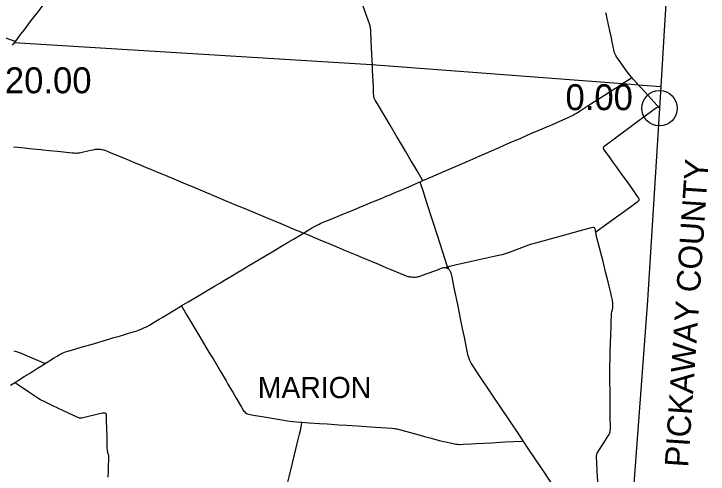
# Model space of a CAD drawing. Extents: x 1597222 to 1925846, y 496284 to 911751.
# Drawn here: x 1727439 to 1756910, y 574335 to 593847 of the extents above; entities that cross this region are included whole.
import ezdxf

# ---------------------------------------------------------------- set-up
doc = ezdxf.new("R2010")
doc.units = 0
for name, color, linetype in [('Default', 7, 'Continuous'), ('GM_X_Adjacent_County_Text', 7, 'Continuous'), ('GM_X_County', 7, 'Continuous'), ('GM_X_County_Road', 7, 'Continuous'), ('GM_X_State_Route', 7, 'Continuous'), ('GM_X_Township', 7, 'Continuous'), ('GM_X_Township_Road', 7, 'Continuous'), ('GM_X_Township_Text', 7, 'Continuous'), ('GM_X_US_Route', 7, 'Continuous')]:
    doc.layers.add(name, color=color, linetype=linetype)

msp = doc.modelspace()

# ---------------------------------------------------------------- linework, layer by layer
at = {"layer": 'Default'}
msp.add_circle((1754847, 589845), 750, dxfattribs=at)
msp.add_circle((1754847, 589845), 750, dxfattribs=at)
msp.add_circle((1754847, 589845), 750, dxfattribs=at)
msp.add_circle((1754847, 589845), 750, dxfattribs=at)
at = {"layer": 'GM_X_County'}
msp.add_lwpolyline([(1724957, 620538), (1728386, 620349), (1731998, 620173), (1732995, 620100), (1742304, 619412), (1747296, 619048), (1751520, 618741), (1756758, 618359), (1755763, 604727), (1755032, 592905), (1754900, 590773), (1754843, 589851), (1754339, 581698), (1753562, 571274), (1753386, 568784), (1753383, 568749), (1753220, 566444), (1752151, 553079)], dxfattribs=at)
at = {"layer": 'GM_X_County_Road'}
for points in [[(1724345, 593802), (1724527, 593740), (1724852, 593628), (1725347, 593455), (1725641, 593354), (1725980, 593232), (1726628, 592999), (1726937, 592890), (1727275, 592768), (1727446, 592708), (1727515, 592688)], [(1751477, 589738), (1751562, 589793), (1751782, 589936), (1752086, 590131), (1752362, 590308), (1752858, 590627), (1753245, 590875), (1753281, 590899)], [(1753281, 590899), (1753507, 591044), (1753611, 591113), (1753665, 591150)], [(1744801, 586780), (1745035, 586882), (1745788, 587207), (1746285, 587422), (1746676, 587591), (1746812, 587650), (1747187, 587814), (1748015, 588172), (1748256, 588276), (1748512, 588388), (1748963, 588584), (1749234, 588701), (1749460, 588798), (1749761, 588929), (1750062, 589058), (1750272, 589150), (1750739, 589351), (1750964, 589452), (1751083, 589507), (1751156, 589545), (1751242, 589593), (1751327, 589644), (1751477, 589738)], [(1727418, 588214), (1727598, 588196), (1727891, 588165), (1728120, 588142), (1728397, 588114), (1728593, 588096), (1728675, 588088), (1728934, 588060), (1729292, 588022), (1729910, 587959), (1730008, 587950), (1730074, 587947), (1730123, 587948), (1730171, 587951), (1730220, 587957), (1730284, 587968), (1730396, 587992), (1730524, 588023), (1730635, 588050), (1730795, 588088), (1730859, 588102), (1730908, 588110), (1730957, 588114), (1731007, 588115), (1731056, 588113), (1731106, 588109), (1731155, 588102), (1731203, 588092), (1731251, 588080), (1731298, 588065), (1731375, 588037), (1731557, 587962), (1731951, 587798), (1732360, 587628), (1732542, 587552), (1732769, 587458), (1733057, 587338), (1733283, 587243), (1733541, 587137), (1733723, 587062), (1733859, 587005), (1734328, 586809), (1734631, 586683), (1735009, 586524), (1735448, 586341), (1735811, 586190), (1736205, 586025), (1736780, 585786), (1737249, 585590), (1737582, 585451), (1738142, 585218), (1738778, 584954), (1739066, 584834), (1739429, 584682), (1739550, 584631), (1739700, 584565), (1739729, 584555)], [(1744684, 586731), (1744795, 586778), (1744801, 586780)], [(1739729, 584555), (1739812, 584604), (1740079, 584764), (1740206, 584839), (1740307, 584894), (1740395, 584938), (1740469, 584973), (1740575, 585017), (1740939, 585165), (1741409, 585359), (1741864, 585546), (1742229, 585695), (1742411, 585770), (1742593, 585845), (1743002, 586013), (1743123, 586064), (1743244, 586114), (1743412, 586182), (1743502, 586220), (1743653, 586284), (1743834, 586361), (1744105, 586479), (1744330, 586577), (1744571, 586683), (1744684, 586731)], [(1745853, 583130), (1745838, 583168), (1745654, 583746), (1745426, 584447), (1745214, 585102), (1745143, 585320), (1744901, 586069), (1744826, 586303), (1744692, 586707), (1744684, 586731)], [(1734547, 581463), (1734840, 581638), (1735178, 581840), (1735572, 582076), (1735952, 582303), (1736178, 582437), (1736375, 582554), (1736643, 582713), (1736910, 582874), (1737079, 582974), (1737445, 583193), (1738093, 583580), (1738404, 583763), (1738615, 583890), (1738840, 584025), (1739079, 584168), (1739305, 584302), (1739729, 584555)], [(1739729, 584555), (1739792, 584532), (1739899, 584489), (1740459, 584255), (1740776, 584121), (1741155, 583965), (1741503, 583820), (1742002, 583611), (1742230, 583516), (1742608, 583358), (1742911, 583233), (1743229, 583100), (1743440, 583010), (1743848, 582839), (1743954, 582795), (1744060, 582752), (1744122, 582731), (1744169, 582718), (1744217, 582707), (1744265, 582699), (1744314, 582693), (1744379, 582689), (1744428, 582689), (1744477, 582691), (1744542, 582697), (1744590, 582705), (1744622, 582712), (1744684, 582731), (1744792, 582769), (1744977, 582836), (1745346, 582973), (1745515, 583035), (1745593, 583064), (1745637, 583079), (1745674, 583088), (1745695, 583091), (1745719, 583094), (1745741, 583094), (1745764, 583092)], [(1745764, 583092), (1745791, 583085), (1745815, 583078), (1745835, 583070), (1745835, 583070)], [(1745835, 583070), (1745856, 583058), (1745883, 583040), (1745897, 583030)], [(1745897, 583030), (1745884, 583060), (1745876, 583080), (1745862, 583106), (1745853, 583130)], [(1745897, 583030), (1745924, 583001), (1745938, 582980), (1745951, 582960), (1745963, 582938), (1745973, 582916), (1745988, 582870), (1746004, 582807), (1746042, 582617), (1746072, 582464), (1746120, 582228), (1746264, 581521), (1746340, 581152), (1746386, 580927), (1746471, 580509), (1746548, 580140), (1746668, 579545), (1746702, 579402), (1746734, 579291), (1746768, 579198), (1746807, 579108), (1746853, 579020), (1746922, 578908), (1747140, 578581), (1747771, 577642), (1748445, 576633), (1748885, 575980), (1749047, 575739)], [(1728769, 579024), (1729125, 579244), (1729280, 579340), (1729378, 579399), (1729451, 579438), (1729495, 579458), (1729555, 579486), (1729632, 579514), (1729726, 579542), (1729883, 579590), (1730292, 579710), (1730812, 579862), (1731048, 579931), (1731236, 579988), (1731519, 580071), (1731686, 580122), (1731870, 580176), (1732058, 580229), (1732183, 580268), (1732263, 580292), (1732562, 580379), (1732656, 580410), (1732733, 580438), (1732840, 580480), (1732930, 580518), (1732990, 580546), (1733063, 580584), (1733192, 580656), (1733390, 580772), (1733601, 580899), (1733756, 580992), (1734136, 581218), (1734348, 581344), (1734488, 581428), (1734547, 581463)], [(1727466, 578211), (1727593, 578291), (1727874, 578466), (1728096, 578605), (1728444, 578820), (1728612, 578925), (1728769, 579024)], [(1727302, 578109), (1727441, 578195), (1727466, 578211)], [(1749047, 575739), (1749287, 575381), (1749764, 574674), (1749864, 574524), (1750804, 573121), (1750848, 573055)]]:
    msp.add_lwpolyline(points, dxfattribs=at)
at = {"layer": 'GM_X_State_Route'}
for points in [[(1753106, 591917), (1753037, 592014), (1752993, 592083), (1752962, 592140), (1752939, 592201), (1752922, 592264), (1752921, 592269), (1752881, 592459), (1752842, 592644), (1752803, 592829), (1752764, 593014), (1752754, 593065), (1752723, 593199), (1752696, 593319), (1752682, 593384), (1752669, 593447), (1752666, 593465), (1752629, 593636), (1752613, 593707), (1752607, 593734), (1752573, 593888), (1752572, 593893)], [(1753727, 591084), (1753685, 591130), (1753665, 591150), (1753579, 591257), (1753432, 591453), (1753244, 591721), (1753106, 591917)], [(1754836, 589871), (1754786, 589923), (1754737, 589975), (1754239, 590522), (1754040, 590740), (1753947, 590842), (1753885, 590911), (1753727, 591084)]]:
    msp.add_lwpolyline(points, dxfattribs=at)
at = {"layer": 'GM_X_Township'}
msp.add_lwpolyline([(1727437, 592635), (1742617, 591697), (1753269, 590901), (1753638, 590868), (1753940, 590844), (1754900, 590773)], dxfattribs=at)
at = {"layer": 'GM_X_Township_Road'}
for points in [[(1742656, 591696), (1742648, 591877), (1742638, 592138), (1742609, 592680), (1742585, 593169), (1742576, 593250), (1742568, 593295), (1742557, 593342), (1742531, 593426), (1742366, 593888), (1742220, 594309), (1742054, 594775), (1741897, 595203), (1741781, 595515), (1741603, 596005), (1741472, 596362), (1741357, 596667), (1741283, 596868), (1741127, 597297), (1740989, 597668), (1740927, 597839), (1740917, 597865)], [(1744801, 586780), (1744778, 586819), (1744563, 587187), (1744421, 587427), (1744296, 587638), (1744063, 588033), (1743904, 588301), (1743687, 588667), (1743410, 589132), (1743184, 589512), (1742874, 590032), (1742781, 590187), (1742750, 590245), (1742732, 590290), (1742724, 590322), (1742717, 590370), (1742712, 590485), (1742703, 590747), (1742668, 591467), (1742656, 591696)], [(1752156, 584595), (1752160, 584604), (1752170, 584617), (1752181, 584628), (1752206, 584649), (1752552, 584900), (1752765, 585054), (1752911, 585160), (1753018, 585236), (1753202, 585373), (1753414, 585527), (1753614, 585671), (1753786, 585798), (1753905, 585886), (1753945, 585913), (1753958, 585924), (1753970, 585935), (1753980, 585948), (1753986, 585962), (1753989, 585978), (1753987, 585994), (1753981, 586010), (1753974, 586025), (1753957, 586053), (1753890, 586146), (1753823, 586239), (1753710, 586401), (1753481, 586721), (1753310, 586962), (1753195, 587122), (1753034, 587349), (1752872, 587576), (1752747, 587750), (1752517, 588069), (1752488, 588109), (1752479, 588123), (1752472, 588138), (1752466, 588153), (1752464, 588169), (1752465, 588185), (1752470, 588200), (1752478, 588214), (1752488, 588227), (1752500, 588238), (1752539, 588268), (1752711, 588395), (1752869, 588512), (1753040, 588640), (1753262, 588808), (1753472, 588966), (1753696, 589133), (1753987, 589347), (1754239, 589530), (1754558, 589760), (1754786, 589923)], [(1745900, 583144), (1745952, 583158), (1746175, 583211), (1746864, 583366), (1747763, 583562), (1748228, 583665), (1748355, 583698), (1748480, 583739), (1749293, 584050), (1749432, 584098), (1749590, 584145), (1750636, 584430), (1751586, 584689), (1751966, 584794), (1752014, 584806), (1752031, 584807), (1752047, 584805), (1752062, 584798), (1752074, 584788), (1752084, 584775), (1752091, 584760), (1752095, 584744), (1752113, 584664), (1752119, 584643), (1752122, 584631), (1752127, 584621), (1752133, 584613), (1752140, 584606), (1752156, 584595)], [(1752238, 573810), (1752204, 574446), (1752183, 574823), (1752171, 575052), (1752171, 575101), (1752174, 575134), (1752181, 575166), (1752191, 575197), (1752204, 575227), (1752228, 575270), (1752272, 575340), (1752476, 575657), (1752601, 575849), (1752673, 575959), (1752708, 576015), (1752723, 576044), (1752737, 576074), (1752742, 576089), (1752750, 576121), (1752755, 576153), (1752757, 576186), (1752759, 576268), (1752753, 576793), (1752750, 577072), (1752747, 577335), (1752745, 577728), (1752745, 577925), (1752744, 578204), (1752743, 578450), (1752742, 578778), (1752742, 578975), (1752746, 579139), (1752755, 579467), (1752772, 579959), (1752778, 580156), (1752783, 580320), (1752789, 580484), (1752794, 580648), (1752798, 580812), (1752805, 581025), (1752809, 581107), (1752815, 581156), (1752826, 581220), (1752847, 581316), (1752862, 581380), (1752867, 581413), (1752871, 581445), (1752872, 581478), (1752870, 581527), (1752863, 581592), (1752850, 581690), (1752836, 581771), (1752813, 581883), (1752778, 582027), (1752710, 582297), (1752663, 582489), (1752555, 582918), (1752448, 583348), (1752233, 584191), (1752162, 584461), (1752151, 584509), (1752147, 584541), (1752147, 584558), (1752149, 584574), (1752153, 584589), (1752156, 584595)], [(1745764, 583092), (1745834, 583121), (1745853, 583130)], [(1745853, 583130), (1745877, 583137), (1745900, 583144)], [(1745897, 583030), (1745892, 583060), (1745892, 583072), (1745891, 583084), (1745892, 583100), (1745894, 583116), (1745900, 583144)], [(1734547, 581463), (1734563, 581437), (1734784, 581073), (1735331, 580158), (1735593, 579722), (1735762, 579441), (1735922, 579174), (1736198, 578711), (1736448, 578287), (1736527, 578153), (1736569, 578080), (1736638, 577962), (1736680, 577891), (1736732, 577808), (1736881, 577553), (1737102, 577174), (1737178, 577046), (1737207, 577006), (1737240, 576970), (1737277, 576937), (1737317, 576909), (1737361, 576887), (1737408, 576872), (1737472, 576857), (1737699, 576821), (1737973, 576775), (1738814, 576631), (1739056, 576591), (1739284, 576564), (1739607, 576535), (1739666, 576531)], [(1727438, 579559), (1727549, 579531), (1727627, 579506), (1727749, 579457), (1727900, 579393), (1728173, 579279), (1728475, 579155), (1728539, 579128), (1728673, 579073), (1728746, 579037), (1728769, 579024)], [(1731443, 574208), (1731450, 574454), (1731460, 574717), (1731468, 574930), (1731470, 575045), (1731469, 575075), (1731468, 575095), (1731464, 575125), (1731455, 575158), (1731432, 575237), (1731421, 575275), (1731416, 575300), (1731412, 575322), (1731410, 575343), (1731407, 575377), (1731405, 575431), (1731399, 575694), (1731393, 575923), (1731377, 576598), (1731373, 576752), (1731370, 576807), (1731368, 576851), (1731367, 576861), (1731364, 576875), (1731360, 576883), (1731357, 576890), (1731353, 576896), (1731348, 576902), (1731341, 576908), (1731335, 576912), (1731327, 576916), (1731320, 576919), (1731312, 576921), (1731304, 576923), (1731287, 576924), (1731255, 576922), (1731206, 576913), (1731020, 576872), (1730430, 576734), (1730317, 576711), (1730293, 576708), (1730268, 576707), (1730253, 576707), (1730236, 576709), (1730221, 576712), (1730204, 576716), (1730158, 576733), (1729757, 576922), (1729549, 577020), (1729058, 577249), (1728718, 577408), (1728573, 577485), (1728502, 577527), (1728324, 577644), (1728077, 577806), (1727682, 578071), (1727503, 578188), (1727466, 578211)], [(1738759, 572761), (1738766, 572788), (1738846, 573107), (1739052, 573934), (1739123, 574221), (1739251, 574747), (1739500, 575751), (1739569, 576022), (1739604, 576182), (1739634, 576343), (1739662, 576505), (1739666, 576531)], [(1739666, 576531), (1739981, 576510), (1740406, 576481), (1740733, 576460), (1741240, 576424), (1741568, 576403), (1742009, 576376), (1742797, 576324), (1743501, 576279), (1743598, 576268), (1743646, 576260), (1743695, 576249), (1743901, 576195), (1744582, 576011), (1744866, 575934), (1745151, 575855), (1745499, 575762), (1746027, 575644), (1746196, 575610), (1746278, 575599), (1746318, 575596), (1746360, 575595), (1746507, 575597), (1746851, 575614), (1747064, 575626), (1747719, 575663), (1748291, 575700), (1748995, 575736), (1749047, 575739)]]:
    msp.add_lwpolyline(points, dxfattribs=at)
at = {"layer": 'GM_X_US_Route'}
msp.add_lwpolyline([(1727384, 592515), (1727515, 592688), (1727591, 592795), (1727718, 592967), (1727869, 593161), (1728173, 593562), (1728421, 593879), (1728721, 594277), (1729024, 594677), (1729678, 595540), (1730065, 596050), (1730291, 596352), (1730598, 596757), (1731142, 597476), (1732319, 599033), (1732626, 599438), (1733063, 600014), (1733230, 600236), (1733873, 601087), (1733875, 601091)], dxfattribs=at)

# ---------------------------------------------------------------- texts
at = {"layer": 'Default'}
for s, p in [('20.00', (1727056, 590482)), ('20.00', (1727056, 590482)), ('0.00', (1750855, 589766)), ('0.00', (1750855, 589766))]:
    msp.add_text(s, height=1100, dxfattribs=at).set_placement(p)
at = {"layer": 'GM_X_Adjacent_County_Text'}
msp.add_text('PICKAWAY COUNTY', height=1000, rotation=86.169, dxfattribs=at).set_placement((1756062, 574603))
at = {"layer": 'GM_X_Township_Text'}
msp.add_text('MARION', height=900, rotation=0, dxfattribs=at).set_placement((1737795, 577556))

doc.saveas('drawing.dxf')
